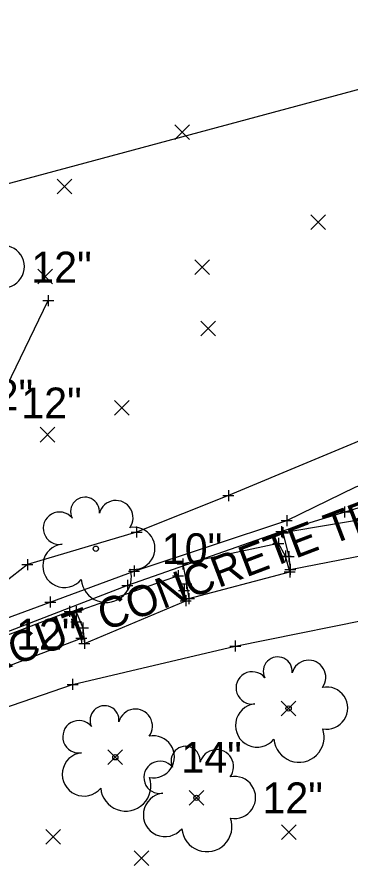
# Model space of a CAD drawing. Extents: x 160138 to 160780, y 488720 to 491073.
# Drawn here: x 160587 to 160617.3, y 489677.7 to 489754.3 of the extents above; entities that cross this region are included whole.
import ezdxf

# ---------------------------------------------------------------- set-up
doc = ezdxf.new("R2010")
doc.units = 0
for name, color, linetype in [('_CIVIL_CONSTRUCTION', 7, 'Continuous'), ('GE_X_Alignment_500_Distances', 7, 'Continuous'), ('RD_X_Concrete_Pad', 7, 'Continuous'), ('RD_X_Text', 7, 'Continuous'), ('RS_Raster1', 7, 'Continuous'), ('SC_Scratch1', 7, 'Continuous'), ('SV_P_Control_Cells_Set', 7, 'Continuous'), ('SV_P_Mon_Cells_Set', 7, 'Continuous'), ('SV_X_Random_Point', 7, 'Continuous'), ('SV_X_Terrain_Boundary', 7, 'Continuous'), ('VG_X_Text', 7, 'Continuous')]:
    doc.layers.add(name, color=color, linetype=linetype)

msp = doc.modelspace()

# ---------------------------------------------------------------- linework, layer by layer
at = {"layer": '_CIVIL_CONSTRUCTION'}
for p, q in [((160601.305, 489743.105), (160602.638, 489744.44)), ((160601.305, 489744.44), (160602.638, 489743.105)), ((160590.624, 489738.176), (160591.957, 489739.511)), ((160590.624, 489739.511), (160591.957, 489738.176)), ((160613.674, 489734.946), (160615.007, 489736.281)), ((160613.674, 489736.281), (160615.007, 489734.946)), ((160603.134, 489730.831), (160604.467, 489732.166)), ((160603.134, 489732.166), (160604.467, 489730.831)), ((160588.874, 489730.005), (160590.207, 489731.34)), ((160588.874, 489731.34), (160590.207, 489730.005)), ((160603.677, 489725.267), (160605.01, 489726.602)), ((160603.677, 489726.602), (160605.01, 489725.267)), ((160595.84, 489718.059), (160597.173, 489719.394)), ((160595.84, 489719.394), (160597.173, 489718.059)), ((160589.074, 489715.624), (160590.408, 489716.959)), ((160589.074, 489716.959), (160590.408, 489715.624)), ((160610.989, 489690.747), (160612.322, 489692.082)), ((160610.989, 489692.082), (160612.322, 489690.747)), ((160595.238, 489686.311), (160596.571, 489687.646)), ((160595.238, 489687.646), (160596.571, 489686.311)), ((160602.612, 489682.624), (160603.945, 489683.959)), ((160602.612, 489683.959), (160603.945, 489682.624)), ((160611.024, 489679.517), (160612.357, 489680.852)), ((160611.024, 489680.852), (160612.357, 489679.517)), ((160589.59, 489679.072), (160590.923, 489680.407)), ((160589.59, 489680.407), (160590.923, 489679.072)), ((160597.61, 489677.14), (160598.944, 489678.475)), ((160597.61, 489678.475), (160598.944, 489677.14))]:
    msp.add_line(p, q, dxfattribs=at)
at = {"layer": 'GE_X_Alignment_500_Distances'}
for points in [[(160621.534, 489717.15), (160606.181, 489710.759), (160597.835, 489707.435), (160587.92, 489704.491), (160584.396, 489701.774), (160576.406, 489698.274), (160571.095, 489699.657), (160571.143, 489703.736), (160568.43, 489703.792), (160567.108, 489700.473), (160566.216, 489695.724), (160561.396, 489691.947), (160554.509, 489692.134), (160553.007, 489689.884), (160552.633, 489686.649), (160552.379, 489683.318), (160552.332, 489681.352), (160553.749, 489678.967), (160558.048, 489677.046), (160562.424, 489674.113), (160566.368, 489663.913), (160565.537, 489659.127), (160562.724, 489647.863)], [(160567.306, 489654.928), (160569.133, 489661.115), (160570.764, 489664.778), (160569.567, 489671.947), (160569.755, 489676.53), (160570.988, 489682.463), (160577.363, 489688.561), (160592.024, 489693.602), (160606.811, 489697.077), (160621.483, 489700.054)]]:
    msp.add_lwpolyline(points, dxfattribs=at)
at = {"layer": 'RD_X_Concrete_Pad'}
for points in [[(160620.98, 489705.834), (160620.389, 489707.729), (160620.155, 489708.888), (160611.141, 489707.386), (160611.673, 489705.217), (160611.799, 489704.052)], [(160611.762, 489703.814), (160611.389, 489705.253), (160610.738, 489706.41), (160602.038, 489704.55), (160602.373, 489702.751), (160602.591, 489701.396)], [(160602.301, 489701.199), (160602.156, 489702.142), (160601.612, 489703.478), (160592.356, 489700.197), (160592.96, 489698.727), (160593.09, 489697.323)], [(160592.827, 489697.813), (160592.353, 489699.297), (160591.743, 489700.234), (160582.82, 489696.835), (160583.474, 489695.225), (160583.555, 489694.287)]]:
    msp.add_lwpolyline(points, close=True, dxfattribs=at)
at = {"layer": 'RS_Raster1'}
for p, q in [((160616.233, 489709.277), (160617.233, 489709.277)), ((160616.733, 489709.777), (160616.733, 489708.777)), ((160616.733, 489709.277), (160616.733, 489709.277))]:
    msp.add_line(p, q, dxfattribs=at)
at = {"layer": 'SC_Scratch1'}
for centre in [(160594.134, 489705.929), (160611.655, 489691.414), (160595.904, 489686.978), (160603.279, 489683.291)]:
    msp.add_circle(centre, 0.24, dxfattribs=at)
for centre, radius, start, end in [((160585.723, 489731.552), 1.915, 259.14531, 101.45961), ((160593.15, 489709.296), 1.317, 354.0047, 205.97412), ((160595.96, 489708.758), 1.553, 323.82996, 165.0376), ((160590.824, 489707.793), 1.471, 39.06254, 279.54124), ((160597.594, 489705.965), 1.915, 259.14531, 101.45961), ((160591.28, 489704.38), 1.974, 96.17219, 320.57371), ((160595.08, 489703.324), 2.284, 184.94757, 19.45715), ((160610.671, 489694.782), 1.317, 354.0047, 205.97412), ((160613.481, 489694.244), 1.553, 323.82996, 165.0376), ((160608.346, 489693.279), 1.471, 39.06254, 279.54124), ((160615.115, 489691.45), 1.915, 259.14531, 101.45961), ((160594.92, 489690.346), 1.317, 354.0047, 205.97412), ((160608.802, 489689.866), 1.974, 96.17219, 320.57371), ((160597.73, 489689.807), 1.553, 323.82996, 165.0376), ((160592.595, 489688.842), 1.471, 39.06254, 279.54124), ((160612.602, 489688.809), 2.284, 184.94757, 19.45715), ((160599.364, 489687.014), 1.915, 259.14531, 101.45961), ((160602.295, 489686.659), 1.317, 354.0047, 205.97412), ((160605.105, 489686.12), 1.553, 323.82996, 165.0376), ((160593.051, 489685.429), 1.974, 96.17219, 320.57371), ((160599.969, 489685.155), 1.471, 39.06254, 279.54124), ((160596.851, 489684.373), 2.284, 184.94757, 19.45715), ((160606.739, 489683.327), 1.915, 259.14531, 101.45961), ((160600.425, 489681.743), 1.974, 96.17219, 320.57371), ((160604.225, 489680.686), 2.284, 184.94757, 19.45715)]:
    msp.add_arc(centre, radius, start, end, dxfattribs=at)
at = {"layer": 'SV_P_Control_Cells_Set'}
for points in [[(160576.55, 489703.778), (160579.917, 489712.897), (160586.034, 489720.686), (160589.811, 489728.475)], [(160570.792, 489697.104), (160575.871, 489695.835), (160582.126, 489698.194), (160589.99, 489701.077), (160597.61, 489703.891), (160611.482, 489708.49), (160617.773, 489711.561), (160624.019, 489713.541), (160631.981, 489716.744), (160639.194, 489717.897), (160645.106, 489719.665)]]:
    msp.add_lwpolyline(points, dxfattribs=at)
at = {"layer": 'SV_P_Mon_Cells_Set'}
msp.add_lwpolyline([(160642.298, 489714.198), (160635.133, 489713.639), (160628.549, 489712.85), (160610.996, 489707.492), (160597, 489702.59), (160583.659, 489697.445), (160573.764, 489689.275), (160563.368, 489687.484)], dxfattribs=at)
at = {"layer": 'SV_X_Random_Point'}
for p, q in [((160589.811, 489728.975), (160589.811, 489727.975)), ((160589.311, 489728.475), (160590.311, 489728.475)), ((160589.811, 489728.475), (160589.811, 489728.475)), ((160605.681, 489710.759), (160606.681, 489710.759)), ((160606.181, 489711.259), (160606.181, 489710.259)), ((160606.181, 489710.759), (160606.181, 489710.759)), ((160610.982, 489708.49), (160611.982, 489708.49)), ((160611.482, 489708.99), (160611.482, 489707.99)), ((160611.482, 489708.49), (160611.482, 489708.49)), ((160597.835, 489707.935), (160597.835, 489706.935)), ((160610.996, 489707.992), (160610.996, 489706.992)), ((160611.141, 489707.886), (160611.141, 489706.886)), ((160597.335, 489707.435), (160598.335, 489707.435)), ((160597.835, 489707.435), (160597.835, 489707.435)), ((160610.496, 489707.492), (160611.496, 489707.492)), ((160610.641, 489707.386), (160611.641, 489707.386)), ((160610.738, 489706.91), (160610.738, 489705.91)), ((160610.996, 489707.492), (160610.996, 489707.492)), ((160611.141, 489707.386), (160611.141, 489707.386)), ((160610.238, 489706.41), (160611.238, 489706.41)), ((160610.738, 489706.41), (160610.738, 489706.41)), ((160610.889, 489705.253), (160611.889, 489705.253)), ((160611.173, 489705.217), (160612.173, 489705.217)), ((160611.389, 489705.753), (160611.389, 489704.753)), ((160611.389, 489705.253), (160611.389, 489705.253)), ((160611.673, 489705.717), (160611.673, 489704.717)), ((160611.673, 489705.217), (160611.673, 489705.217)), ((160587.42, 489704.491), (160588.42, 489704.491)), ((160587.92, 489704.991), (160587.92, 489703.991)), ((160587.92, 489704.491), (160587.92, 489704.491)), ((160601.538, 489704.55), (160602.538, 489704.55)), ((160602.038, 489705.05), (160602.038, 489704.05)), ((160602.038, 489704.55), (160602.038, 489704.55)), ((160611.799, 489704.552), (160611.799, 489703.552)), ((160597.11, 489703.891), (160598.11, 489703.891)), ((160597.61, 489704.391), (160597.61, 489703.391)), ((160597.61, 489703.891), (160597.61, 489703.891)), ((160601.612, 489703.978), (160601.612, 489702.978)), ((160611.262, 489703.814), (160612.262, 489703.814)), ((160611.299, 489704.052), (160612.299, 489704.052)), ((160611.762, 489704.314), (160611.762, 489703.314)), ((160611.762, 489703.814), (160611.762, 489703.814)), ((160611.799, 489704.052), (160611.799, 489704.052)), ((160597, 489703.09), (160597, 489702.09)), ((160601.112, 489703.478), (160602.112, 489703.478)), ((160601.612, 489703.478), (160601.612, 489703.478)), ((160602.373, 489703.251), (160602.373, 489702.251)), ((160596.5, 489702.59), (160597.5, 489702.59)), ((160597, 489702.59), (160597, 489702.59)), ((160601.656, 489702.142), (160602.656, 489702.142)), ((160601.873, 489702.751), (160602.873, 489702.751)), ((160602.156, 489702.642), (160602.156, 489701.642)), ((160602.156, 489702.142), (160602.156, 489702.142)), ((160602.373, 489702.751), (160602.373, 489702.751)), ((160589.99, 489701.577), (160589.99, 489700.577)), ((160602.091, 489701.396), (160603.091, 489701.396)), ((160602.301, 489701.699), (160602.301, 489700.699)), ((160602.591, 489701.896), (160602.591, 489700.896)), ((160602.591, 489701.396), (160602.591, 489701.396)), ((160589.49, 489701.077), (160590.49, 489701.077)), ((160589.99, 489701.077), (160589.99, 489701.077)), ((160591.743, 489700.734), (160591.743, 489699.734)), ((160592.356, 489700.697), (160592.356, 489699.697)), ((160601.801, 489701.199), (160602.801, 489701.199)), ((160602.301, 489701.199), (160602.301, 489701.199)), ((160591.243, 489700.234), (160592.243, 489700.234)), ((160591.743, 489700.234), (160591.743, 489700.234)), ((160591.856, 489700.197), (160592.856, 489700.197)), ((160592.356, 489700.197), (160592.356, 489700.197)), ((160591.853, 489699.297), (160592.853, 489699.297)), ((160592.353, 489699.797), (160592.353, 489698.797)), ((160592.353, 489699.297), (160592.353, 489699.297)), ((160592.96, 489699.227), (160592.96, 489698.227)), ((160592.46, 489698.727), (160593.46, 489698.727)), ((160592.827, 489698.313), (160592.827, 489697.313)), ((160592.96, 489698.727), (160592.96, 489698.727)), ((160592.327, 489697.813), (160593.327, 489697.813)), ((160592.827, 489697.813), (160592.827, 489697.813)), ((160593.09, 489697.823), (160593.09, 489696.823)), ((160606.811, 489697.577), (160606.811, 489696.577)), ((160592.59, 489697.323), (160593.59, 489697.323)), ((160593.09, 489697.323), (160593.09, 489697.323)), ((160606.311, 489697.077), (160607.311, 489697.077)), ((160606.811, 489697.077), (160606.811, 489697.077)), ((160592.024, 489694.102), (160592.024, 489693.102)), ((160591.524, 489693.602), (160592.524, 489693.602)), ((160592.024, 489693.602), (160592.024, 489693.602))]:
    msp.add_line(p, q, dxfattribs=at)
at = {"layer": 'SV_X_Terrain_Boundary'}
msp.add_lwpolyline([(160514.912, 489637.894), (160547.865, 489638.238), (160565.434, 489639.08), (160616.189, 489674.183), (160652.272, 489681.356), (160684.014, 489678.351), (160707.031, 489678.823), (160736.83, 489679.671), (160750.025, 489679.19), (160759.846, 489681.649), (160765.268, 489684.51), (160772.898, 489693.362), (160771.249, 489707.538), (160769.281, 489717.032), (160767.493, 489724.397), (160754.691, 489734.763), (160746.199, 489734.784), (160717.641, 489733.306), (160642.598, 489754.256), (160573.958, 489735.815), (160560.406, 489729.318), (160491.054, 489700.611)], dxfattribs=at)

# ---------------------------------------------------------------- texts
at = {"layer": 'RD_X_Text'}
msp.add_text("UNDERCUT CONCRETE TROUGH'S", height=2.8, rotation=20.84892, dxfattribs=at).set_placement((160574.362, 489690.574))
at = {"layer": 'VG_X_Text'}
for s, p in [('12"', (160588.263, 489730.116)), ('12"', (160582.941, 489718.495)), ('12"', (160587.356, 489717.77)), ('10"', (160600.134, 489704.529)), ('12"', (160586.887, 489696.767)), ('14"', (160601.904, 489685.578)), ('12"', (160609.279, 489681.891))]:
    msp.add_text(s, height=2.8, dxfattribs=at).set_placement(p)

doc.saveas('drawing.dxf')
